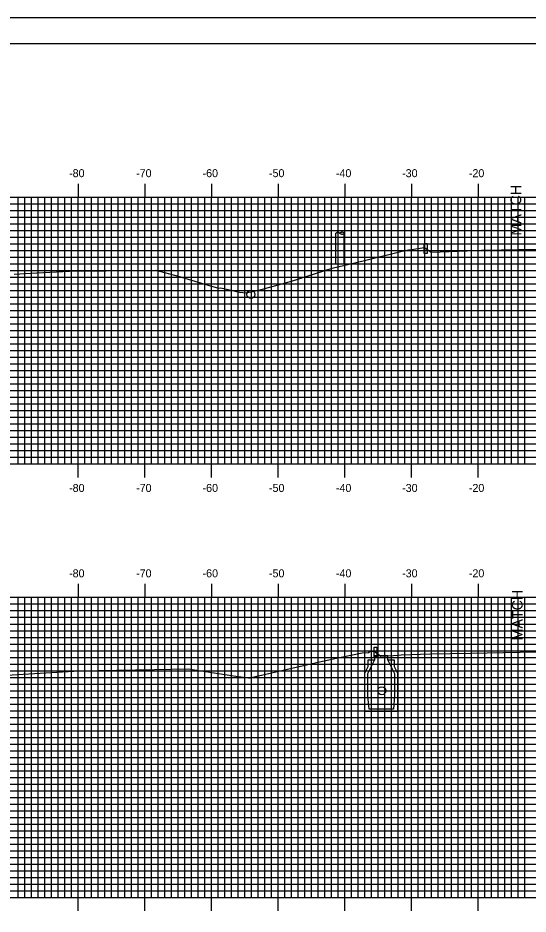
# Model space of a CAD drawing. Extents: x 858052 to 858395, y 364366 to 364586.
# Drawn here: x 858128.3 to 858204.8, y 364451.3 to 364585.7 of the extents above; entities that cross this region are included whole.
import ezdxf

# ---------------------------------------------------------------- set-up
doc = ezdxf.new("R2010")
doc.units = 0
for name, color, linetype in [('ANNOTATION', 7, 'Continuous'), ('BORDER', 7, 'Continuous'), ('H_V ANNOTATION', 7, 'Continuous'), ('M_Roadway_Centerline', 7, 'Continuous'), ('MAJOR', 7, 'Continuous'), ('MINOR', 7, 'Continuous'), ('PLOT BOUNDARY', 7, 'Continuous'), ('S_Curb_Type_1', 7, 'Continuous'), ('S_Drainage_CB', 7, 'Continuous'), ('S_Drainage_Invert', 7, 'Continuous'), ('S_Roadway_Centerline', 7, 'Continuous'), ('S_Utilities_Pole_Power', 7, 'Continuous')]:
    doc.layers.add(name, color=color, linetype=linetype)

msp = doc.modelspace()

# ---------------------------------------------------------------- linework, layer by layer
at = {"layer": 'BORDER'}
msp.add_lwpolyline([(858067.76, 364371.79), (858387.76, 364371.79), (858387.76, 364581.79), (858067.76, 364581.79)], close=True, dxfattribs=at)
at = {"layer": 'MAJOR'}
for p, q in [((858137.36, 364560.79), (858137.36, 364558.79)), ((858147.36, 364560.79), (858147.36, 364558.79)), ((858157.36, 364560.79), (858157.36, 364558.79)), ((858167.36, 364560.79), (858167.36, 364558.79)), ((858177.36, 364560.79), (858177.36, 364558.79)), ((858187.36, 364560.79), (858187.36, 364558.79)), ((858197.36, 364560.79), (858197.36, 364558.79)), ((858077.36, 364558.79), (858357.36, 364558.79)), ((858077.36, 364558.79), (858357.36, 364558.79)), ((858137.36, 364518.79), (858137.36, 364558.79)), ((858147.36, 364518.79), (858147.36, 364558.79)), ((858157.36, 364518.79), (858157.36, 364558.79)), ((858167.36, 364518.79), (858167.36, 364558.79)), ((858177.36, 364518.79), (858177.36, 364558.79)), ((858187.36, 364518.79), (858187.36, 364558.79)), ((858197.36, 364518.79), (858197.36, 364558.79)), ((858077.36, 364553.79), (858357.36, 364553.79)), ((858077.36, 364548.79), (858357.36, 364548.79)), ((858077.36, 364543.79), (858357.36, 364543.79)), ((858077.36, 364538.79), (858357.36, 364538.79)), ((858077.36, 364533.79), (858357.36, 364533.79)), ((858077.36, 364528.79), (858357.36, 364528.79)), ((858077.36, 364523.79), (858357.36, 364523.79)), ((858077.36, 364518.79), (858357.36, 364518.79)), ((858077.36, 364518.79), (858357.36, 364518.79)), ((858137.36, 364516.78), (858137.36, 364518.79)), ((858147.36, 364516.78), (858147.36, 364518.79)), ((858157.36, 364516.78), (858157.36, 364518.79)), ((858167.36, 364516.78), (858167.36, 364518.79)), ((858177.36, 364516.78), (858177.36, 364518.79)), ((858187.36, 364516.78), (858187.36, 364518.79)), ((858197.36, 364516.78), (858197.36, 364518.79)), ((858137.36, 364500.79), (858137.36, 364498.79)), ((858147.36, 364500.79), (858147.36, 364498.79)), ((858157.36, 364500.79), (858157.36, 364498.79)), ((858167.36, 364500.79), (858167.36, 364498.79)), ((858177.36, 364500.79), (858177.36, 364498.79)), ((858187.36, 364500.79), (858187.36, 364498.79)), ((858197.36, 364500.79), (858197.36, 364498.79)), ((858077.36, 364498.79), (858357.36, 364498.79)), ((858077.36, 364498.79), (858357.36, 364498.79)), ((858137.36, 364453.79), (858137.36, 364498.79)), ((858147.36, 364453.79), (858147.36, 364498.79)), ((858157.36, 364453.79), (858157.36, 364498.79)), ((858167.36, 364453.79), (858167.36, 364498.79)), ((858177.36, 364453.79), (858177.36, 364498.79)), ((858187.36, 364453.79), (858187.36, 364498.79)), ((858197.36, 364453.79), (858197.36, 364498.79)), ((858077.36, 364493.79), (858357.36, 364493.79)), ((858077.36, 364488.79), (858357.36, 364488.79)), ((858077.36, 364483.79), (858357.36, 364483.79)), ((858077.36, 364478.79), (858357.36, 364478.79)), ((858077.36, 364473.79), (858357.36, 364473.79)), ((858077.36, 364468.79), (858357.36, 364468.79)), ((858077.36, 364463.79), (858357.36, 364463.79)), ((858077.36, 364458.79), (858357.36, 364458.79)), ((858077.36, 364453.79), (858357.36, 364453.79)), ((858077.36, 364453.79), (858357.36, 364453.79)), ((858137.36, 364451.78), (858137.36, 364453.79)), ((858147.36, 364451.78), (858147.36, 364453.79)), ((858157.36, 364451.78), (858157.36, 364453.79)), ((858167.36, 364451.78), (858167.36, 364453.79)), ((858177.36, 364451.78), (858177.36, 364453.79)), ((858187.36, 364451.78), (858187.36, 364453.79)), ((858197.36, 364451.78), (858197.36, 364453.79))]:
    msp.add_line(p, q, dxfattribs=at)
at = {"layer": 'MINOR'}
for p, q in [((858128.36, 364518.79), (858128.36, 364558.79)), ((858129.36, 364518.79), (858129.36, 364558.79)), ((858130.36, 364518.79), (858130.36, 364558.79)), ((858131.36, 364518.79), (858131.36, 364558.79)), ((858132.36, 364518.79), (858132.36, 364558.79)), ((858133.36, 364518.79), (858133.36, 364558.79)), ((858134.36, 364518.79), (858134.36, 364558.79)), ((858135.36, 364518.79), (858135.36, 364558.79)), ((858136.36, 364518.79), (858136.36, 364558.79)), ((858138.36, 364518.79), (858138.36, 364558.79)), ((858139.36, 364518.79), (858139.36, 364558.79)), ((858140.36, 364518.79), (858140.36, 364558.79)), ((858141.36, 364518.79), (858141.36, 364558.79)), ((858142.36, 364518.79), (858142.36, 364558.79)), ((858143.36, 364518.79), (858143.36, 364558.79)), ((858144.36, 364518.79), (858144.36, 364558.79)), ((858145.36, 364518.79), (858145.36, 364558.79)), ((858146.36, 364518.79), (858146.36, 364558.79)), ((858148.36, 364518.79), (858148.36, 364558.79)), ((858149.36, 364518.79), (858149.36, 364558.79)), ((858150.36, 364518.79), (858150.36, 364558.79)), ((858151.36, 364518.79), (858151.36, 364558.79)), ((858152.36, 364518.79), (858152.36, 364558.79)), ((858153.36, 364518.79), (858153.36, 364558.79)), ((858154.36, 364518.79), (858154.36, 364558.79)), ((858155.36, 364518.79), (858155.36, 364558.79)), ((858156.36, 364518.79), (858156.36, 364558.79)), ((858158.36, 364518.79), (858158.36, 364558.79)), ((858159.36, 364518.79), (858159.36, 364558.79)), ((858160.36, 364518.79), (858160.36, 364558.79)), ((858161.36, 364518.79), (858161.36, 364558.79)), ((858162.36, 364518.79), (858162.36, 364558.79)), ((858163.36, 364518.79), (858163.36, 364558.79)), ((858164.36, 364518.79), (858164.36, 364558.79)), ((858165.36, 364518.79), (858165.36, 364558.79)), ((858166.36, 364518.79), (858166.36, 364558.79)), ((858168.36, 364518.79), (858168.36, 364558.79)), ((858169.36, 364518.79), (858169.36, 364558.79)), ((858170.36, 364518.79), (858170.36, 364558.79)), ((858171.36, 364518.79), (858171.36, 364558.79)), ((858172.36, 364518.79), (858172.36, 364558.79)), ((858173.36, 364518.79), (858173.36, 364558.79)), ((858174.36, 364518.79), (858174.36, 364558.79)), ((858175.36, 364518.79), (858175.36, 364558.79)), ((858176.36, 364518.79), (858176.36, 364558.79)), ((858178.36, 364518.79), (858178.36, 364558.79)), ((858179.36, 364518.79), (858179.36, 364558.79)), ((858180.36, 364518.79), (858180.36, 364558.79)), ((858181.36, 364518.79), (858181.36, 364558.79)), ((858182.36, 364518.79), (858182.36, 364558.79)), ((858183.36, 364518.79), (858183.36, 364558.79)), ((858184.36, 364518.79), (858184.36, 364558.79)), ((858185.36, 364518.79), (858185.36, 364558.79)), ((858186.36, 364518.79), (858186.36, 364558.79)), ((858188.36, 364518.79), (858188.36, 364558.79)), ((858189.36, 364518.79), (858189.36, 364558.79)), ((858190.36, 364518.79), (858190.36, 364558.79)), ((858191.36, 364518.79), (858191.36, 364558.79)), ((858192.36, 364518.79), (858192.36, 364558.79)), ((858193.36, 364518.79), (858193.36, 364558.79)), ((858194.36, 364518.79), (858194.36, 364558.79)), ((858195.36, 364518.79), (858195.36, 364558.79)), ((858196.36, 364518.79), (858196.36, 364558.79)), ((858198.36, 364518.79), (858198.36, 364558.79)), ((858199.36, 364518.79), (858199.36, 364558.79)), ((858200.36, 364518.79), (858200.36, 364558.79)), ((858201.36, 364518.79), (858201.36, 364558.79)), ((858202.36, 364518.79), (858202.36, 364558.79)), ((858203.36, 364518.79), (858203.36, 364558.79)), ((858204.36, 364518.79), (858204.36, 364558.79)), ((858077.36, 364557.79), (858357.36, 364557.79)), ((858077.36, 364556.79), (858357.36, 364556.79)), ((858077.36, 364555.79), (858357.36, 364555.79)), ((858077.36, 364554.79), (858357.36, 364554.79)), ((858077.36, 364552.79), (858357.36, 364552.79)), ((858077.36, 364551.79), (858357.36, 364551.79)), ((858077.36, 364550.79), (858357.36, 364550.79)), ((858077.36, 364549.79), (858357.36, 364549.79)), ((858077.36, 364547.79), (858357.36, 364547.79)), ((858077.36, 364546.79), (858357.36, 364546.79)), ((858077.36, 364545.79), (858357.36, 364545.79)), ((858077.36, 364544.79), (858357.36, 364544.79)), ((858077.36, 364542.79), (858357.36, 364542.79)), ((858077.36, 364541.79), (858357.36, 364541.79)), ((858077.36, 364540.79), (858357.36, 364540.79)), ((858077.36, 364539.79), (858357.36, 364539.79)), ((858077.36, 364537.79), (858357.36, 364537.79)), ((858077.36, 364536.79), (858357.36, 364536.79)), ((858077.36, 364535.79), (858357.36, 364535.79)), ((858077.36, 364534.79), (858357.36, 364534.79)), ((858077.36, 364532.79), (858357.36, 364532.79)), ((858077.36, 364531.79), (858357.36, 364531.79)), ((858077.36, 364530.79), (858357.36, 364530.79)), ((858077.36, 364529.79), (858357.36, 364529.79)), ((858077.36, 364527.79), (858357.36, 364527.79)), ((858077.36, 364526.79), (858357.36, 364526.79)), ((858077.36, 364525.79), (858357.36, 364525.79)), ((858077.36, 364524.79), (858357.36, 364524.79)), ((858077.36, 364522.79), (858357.36, 364522.79)), ((858077.36, 364521.79), (858357.36, 364521.79)), ((858077.36, 364520.79), (858357.36, 364520.79)), ((858077.36, 364519.79), (858357.36, 364519.79)), ((858128.36, 364453.79), (858128.36, 364498.79)), ((858129.36, 364453.79), (858129.36, 364498.79)), ((858130.36, 364453.79), (858130.36, 364498.79)), ((858131.36, 364453.79), (858131.36, 364498.79)), ((858132.36, 364453.79), (858132.36, 364498.79)), ((858133.36, 364453.79), (858133.36, 364498.79)), ((858134.36, 364453.79), (858134.36, 364498.79)), ((858135.36, 364453.79), (858135.36, 364498.79)), ((858136.36, 364453.79), (858136.36, 364498.79)), ((858138.36, 364453.79), (858138.36, 364498.79)), ((858139.36, 364453.79), (858139.36, 364498.79)), ((858140.36, 364453.79), (858140.36, 364498.79)), ((858141.36, 364453.79), (858141.36, 364498.79)), ((858142.36, 364453.79), (858142.36, 364498.79)), ((858143.36, 364453.79), (858143.36, 364498.79)), ((858144.36, 364453.79), (858144.36, 364498.79)), ((858145.36, 364453.79), (858145.36, 364498.79)), ((858146.36, 364453.79), (858146.36, 364498.79)), ((858148.36, 364453.79), (858148.36, 364498.79)), ((858149.36, 364453.79), (858149.36, 364498.79)), ((858150.36, 364453.79), (858150.36, 364498.79)), ((858151.36, 364453.79), (858151.36, 364498.79)), ((858152.36, 364453.79), (858152.36, 364498.79)), ((858153.36, 364453.79), (858153.36, 364498.79)), ((858154.36, 364453.79), (858154.36, 364498.79)), ((858155.36, 364453.79), (858155.36, 364498.79)), ((858156.36, 364453.79), (858156.36, 364498.79)), ((858158.36, 364453.79), (858158.36, 364498.79)), ((858159.36, 364453.79), (858159.36, 364498.79)), ((858160.36, 364453.79), (858160.36, 364498.79)), ((858161.36, 364453.79), (858161.36, 364498.79)), ((858162.36, 364453.79), (858162.36, 364498.79)), ((858163.36, 364453.79), (858163.36, 364498.79)), ((858164.36, 364453.79), (858164.36, 364498.79)), ((858165.36, 364453.79), (858165.36, 364498.79)), ((858166.36, 364453.79), (858166.36, 364498.79)), ((858168.36, 364453.79), (858168.36, 364498.79)), ((858169.36, 364453.79), (858169.36, 364498.79)), ((858170.36, 364453.79), (858170.36, 364498.79)), ((858171.36, 364453.79), (858171.36, 364498.79)), ((858172.36, 364453.79), (858172.36, 364498.79)), ((858173.36, 364453.79), (858173.36, 364498.79)), ((858174.36, 364453.79), (858174.36, 364498.79)), ((858175.36, 364453.79), (858175.36, 364498.79)), ((858176.36, 364453.79), (858176.36, 364498.79)), ((858178.36, 364453.79), (858178.36, 364498.79)), ((858179.36, 364453.79), (858179.36, 364498.79)), ((858180.36, 364453.79), (858180.36, 364498.79)), ((858181.36, 364453.79), (858181.36, 364498.79)), ((858182.36, 364453.79), (858182.36, 364498.79)), ((858183.36, 364453.79), (858183.36, 364498.79)), ((858184.36, 364453.79), (858184.36, 364498.79)), ((858185.36, 364453.79), (858185.36, 364498.79)), ((858186.36, 364453.79), (858186.36, 364498.79)), ((858188.36, 364453.79), (858188.36, 364498.79)), ((858189.36, 364453.79), (858189.36, 364498.79)), ((858190.36, 364453.79), (858190.36, 364498.79)), ((858191.36, 364453.79), (858191.36, 364498.79)), ((858192.36, 364453.79), (858192.36, 364498.79)), ((858193.36, 364453.79), (858193.36, 364498.79)), ((858194.36, 364453.79), (858194.36, 364498.79)), ((858195.36, 364453.79), (858195.36, 364498.79)), ((858196.36, 364453.79), (858196.36, 364498.79)), ((858198.36, 364453.79), (858198.36, 364498.79)), ((858199.36, 364453.79), (858199.36, 364498.79)), ((858200.36, 364453.79), (858200.36, 364498.79)), ((858201.36, 364453.79), (858201.36, 364498.79)), ((858202.36, 364453.79), (858202.36, 364498.79)), ((858203.36, 364453.79), (858203.36, 364498.79)), ((858204.36, 364453.79), (858204.36, 364498.79)), ((858077.36, 364497.79), (858357.36, 364497.79)), ((858077.36, 364496.79), (858357.36, 364496.79)), ((858077.36, 364495.79), (858357.36, 364495.79)), ((858077.36, 364494.79), (858357.36, 364494.79)), ((858077.36, 364492.79), (858357.36, 364492.79)), ((858077.36, 364491.79), (858357.36, 364491.79)), ((858077.36, 364490.79), (858357.36, 364490.79)), ((858077.36, 364489.79), (858357.36, 364489.79)), ((858077.36, 364487.79), (858357.36, 364487.79)), ((858077.36, 364486.79), (858357.36, 364486.79)), ((858077.36, 364485.79), (858357.36, 364485.79)), ((858077.36, 364484.79), (858357.36, 364484.79)), ((858077.36, 364482.79), (858357.36, 364482.79)), ((858077.36, 364481.79), (858357.36, 364481.79)), ((858077.36, 364480.79), (858357.36, 364480.79)), ((858077.36, 364479.79), (858357.36, 364479.79)), ((858077.36, 364477.79), (858357.36, 364477.79)), ((858077.36, 364476.79), (858357.36, 364476.79)), ((858077.36, 364475.79), (858357.36, 364475.79)), ((858077.36, 364474.79), (858357.36, 364474.79)), ((858077.36, 364472.79), (858357.36, 364472.79)), ((858077.36, 364471.79), (858357.36, 364471.79)), ((858077.36, 364470.79), (858357.36, 364470.79)), ((858077.36, 364469.79), (858357.36, 364469.79)), ((858077.36, 364467.79), (858357.36, 364467.79)), ((858077.36, 364466.79), (858357.36, 364466.79)), ((858077.36, 364465.79), (858357.36, 364465.79)), ((858077.36, 364464.79), (858357.36, 364464.79)), ((858077.36, 364462.79), (858357.36, 364462.79)), ((858077.36, 364461.79), (858357.36, 364461.79)), ((858077.36, 364460.79), (858357.36, 364460.79)), ((858077.36, 364459.79), (858357.36, 364459.79)), ((858077.36, 364457.79), (858357.36, 364457.79)), ((858077.36, 364456.79), (858357.36, 364456.79)), ((858077.36, 364455.79), (858357.36, 364455.79)), ((858077.36, 364454.79), (858357.36, 364454.79))]:
    msp.add_line(p, q, dxfattribs=at)
at = {"layer": 'PLOT BOUNDARY'}
msp.add_lwpolyline([(858051.57, 364365.67), (858391.57, 364365.67), (858391.57, 364585.67), (858051.57, 364585.67)], close=True, dxfattribs=at)
at = {"layer": 'S_Curb_Type_1'}
for points in [[(858189.26, 364551.84), (858189.68, 364551.84), (858189.68, 364550.34), (858189.26, 364550.34)], [(858189.26, 364551.84), (858189.68, 364551.84), (858189.68, 364550.34), (858189.26, 364550.34)], [(858181.73, 364491.3), (858182.15, 364491.3), (858182.15, 364489.8), (858181.73, 364489.8)], [(858181.73, 364491.3), (858182.15, 364491.3), (858182.15, 364489.8), (858181.73, 364489.8)]]:
    msp.add_lwpolyline(points, close=True, dxfattribs=at)
at = {"layer": 'S_Drainage_CB'}
for p, q in [((858181.8, 364489.35), (858180.82, 364489.35)), ((858180.82, 364489.35), (858180.82, 364488.36)), ((858180.82, 364487.35), (858181.8, 364489.35)), ((858184.82, 364489.35), (858183.8, 364489.35)), ((858183.8, 364489.35), (858184.82, 364487.35)), ((858184.82, 364488.36), (858184.82, 364489.35)), ((858180.82, 364488.36), (858180.32, 364487.35)), ((858185.31, 364487.35), (858184.82, 364488.36)), ((858180.32, 364487.35), (858180.32, 364481.7)), ((858180.82, 364484.03), (858180.82, 364487.35)), ((858184.82, 364487.35), (858184.82, 364484.03)), ((858185.31, 364481.7), (858185.31, 364487.35)), ((858180.98, 364482.03), (858180.82, 364484.03)), ((858184.82, 364484.03), (858184.65, 364482.03)), ((858180.32, 364481.7), (858185.31, 364481.7)), ((858184.65, 364482.03), (858180.98, 364482.03))]:
    msp.add_line(p, q, dxfattribs=at)
msp.add_lwpolyline([(858184.29, 364489.39), (858183.8, 364489.39), (858183.8, 364490.01), (858181.8, 364490.01), (858181.8, 364489.39), (858181.31, 364489.39)], dxfattribs=at)
at = {"layer": 'S_Drainage_Invert'}
for centre in [(858163.27, 364544.2), (858163.27, 364544.2), (858182.89, 364484.77), (858182.89, 364484.77)]:
    msp.add_circle(centre, 0.6, dxfattribs=at)
at = {"layer": 'S_Roadway_Centerline'}
for points in [[(858127.75, 364547.23), (858131.14, 364547.46), (858136.05, 364547.69), (858147.1, 364547.82), (858149.01, 364547.86), (858152.37, 364546.97), (858156.83, 364545.61), (858158.38, 364545.16), (858158.73, 364545.18), (858161.56, 364544.56), (858162.56, 364544.44), (858164.46, 364544.84), (858169.34, 364546.22), (858175.47, 364548.13), (858179.07, 364548.98), (858180.52, 364549.37), (858185.97, 364550.67), (858186.89, 364550.87), (858187.11, 364550.89), (858189.26, 364551.25), (858189.44, 364551.16), (858190.28, 364550.56), (858197.05, 364550.8), (858197.87, 364550.85), (858200.85, 364550.9), (858211.29, 364551.11)], [(858125.73, 364487.08), (858136.7, 364487.71), (858137.41, 364487.77), (858148.81, 364487.99), (858153.84, 364488.06), (858161, 364486.97), (858162.9, 364486.74), (858163.1, 364486.7), (858163.17, 364486.71), (858163.3, 364486.75), (858173.55, 364489.1), (858176.82, 364489.81), (858179.96, 364490.45), (858180.89, 364490.53), (858181.1, 364490.65), (858181.41, 364490.7), (858181.45, 364490.69), (858181.73, 364490.71), (858181.96, 364490.59), (858182.76, 364489.97), (858184.63, 364490.06), (858185.78, 364490.15), (858190.14, 364490.34), (858196.2, 364490.43), (858203.63, 364490.57), (858208.81, 364490.66)]]:
    msp.add_lwpolyline(points, dxfattribs=at)
at = {"layer": 'S_Utilities_Pole_Power'}
for p, q in [((858175.99, 364553.39), (858176.15, 364553.5)), ((858175.99, 364553.39), (858176.15, 364553.5)), ((858175.99, 364548.77), (858175.99, 364553.39)), ((858175.99, 364548.77), (858175.99, 364553.39)), ((858176.46, 364553.5), (858176.62, 364553.39)), ((858176.46, 364553.5), (858176.62, 364553.39)), ((858176.77, 364553.5), (858176.62, 364553.39)), ((858176.77, 364553.5), (858176.62, 364553.39)), ((858176.62, 364553.39), (858176.77, 364553.28)), ((858176.62, 364553.39), (858176.77, 364553.28)), ((858177.24, 364553.39), (858177.08, 364553.5)), ((858177.24, 364553.39), (858177.08, 364553.5)), ((858177.08, 364553.28), (858177.24, 364553.39)), ((858177.08, 364553.28), (858177.24, 364553.39)), ((858177.24, 364548.77), (858177.24, 364553.39)), ((858177.24, 364548.77), (858177.24, 364553.39))]:
    msp.add_line(p, q, dxfattribs=at)
for centre, start, end in [((858176.3, 364553.28), 90, 125.2644), ((858176.3, 364553.28), 90, 125.2644), ((858176.3, 364553.28), 54.7356, 90), ((858176.3, 364553.28), 54.7356, 90), ((858176.93, 364553.28), 90, 125.2644), ((858176.93, 364553.28), 90, 125.2644), ((858176.93, 364553.28), 54.7356, 90), ((858176.93, 364553.28), 54.7356, 90), ((858176.93, 364553.5), 234.7356, 270), ((858176.93, 364553.5), 234.7356, 270), ((858176.93, 364553.5), 270, 305.2644), ((858176.93, 364553.5), 270, 305.2644)]:
    msp.add_arc(centre, 0.271, start, end, dxfattribs=at)

# ---------------------------------------------------------------- texts
at = {"layer": 'ANNOTATION'}
for p in [(858203.8, 364553.04), (858204.02, 364492.32), (858204.02, 364492.32)]:
    msp.add_text('MATCH', height=1.6, rotation=90, dxfattribs=at).set_placement(p)
at = {"layer": 'H_V ANNOTATION'}
for s, p in [('-80', (858135.99, 364561.79)), ('-70', (858146.04, 364561.79)), ('-60', (858156.01, 364561.79)), ('-50', (858165.97, 364561.79)), ('-40', (858176.01, 364561.79)), ('-30', (858185.94, 364561.79)), ('-20', (858195.95, 364561.79)), ('-80', (858135.99, 364514.59)), ('-70', (858146.04, 364514.59)), ('-60', (858156.01, 364514.59)), ('-50', (858165.97, 364514.59)), ('-40', (858176.01, 364514.59)), ('-30', (858185.94, 364514.59)), ('-20', (858195.95, 364514.59)), ('-80', (858135.99, 364501.79)), ('-70', (858146.04, 364501.79)), ('-60', (858156.01, 364501.79)), ('-50', (858165.97, 364501.79)), ('-40', (858176.01, 364501.79)), ('-30', (858185.94, 364501.79)), ('-20', (858195.95, 364501.79))]:
    msp.add_text(s, height=1.2, dxfattribs=at).set_placement(p)
at = {"layer": 'M_Roadway_Centerline'}
for s, p in [('C', (858131.13, 364547.46)), ('L', (858131.14, 364547.46)), ('C', (858137.4, 364487.77)), ('L', (858137.41, 364487.77))]:
    msp.add_text(s, height=0.0146, dxfattribs=at).set_placement(p)

doc.saveas('drawing.dxf')
